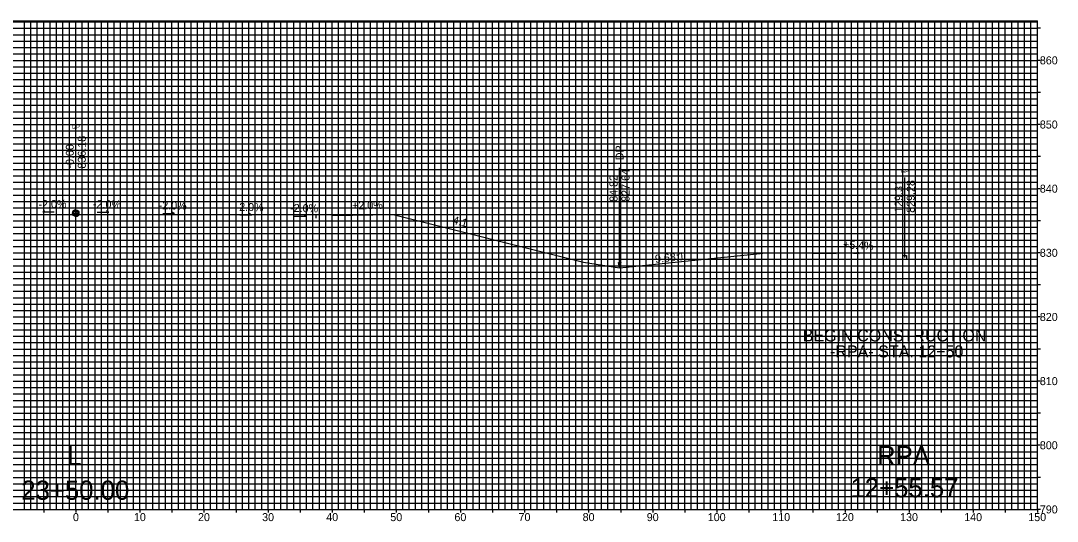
# Model space of a CAD drawing. Extents: x -153 to 153, y 788 to 866.
# Drawn here: x -8.6 to 153.1, y 788.2 to 866.2 of the extents above; entities that cross this region are included whole.
import ezdxf

# ---------------------------------------------------------------- set-up
doc = ezdxf.new("R2010")
doc.units = 0
for name, color, linetype in [('Exist Utilities Power Transformer CELL', 7, 'Continuous'), ('P_NCDOT_XS_Label_Grade_Point', 7, 'Continuous'), ('P_NCDOT_XS_Label_Grading_Side_Slope', 7, 'Continuous'), ('P_NCDOT_XS_Label_Slope_Superelevation', 7, 'Continuous'), ('P_NCDOT_XS_Leader_Line', 7, 'Continuous'), ('P_NCDOT_XS_Sheet_Alignment_Station_Label', 7, 'Continuous'), ('P_NCDOT_XS_Sheet_Annotation_Label', 7, 'Continuous'), ('P_NCDOT_XS_Sheet_Grid_Border', 7, 'Continuous'), ('P_NCDOT_XS_Slope_Label', 7, 'Continuous'), ('P_RDY_XS_EOT_Tick_Mark', 7, 'Continuous'), ('Prop XS Grade Point', 7, 'Continuous'), ('Prop XS Label Slope Superelevation', 7, 'Continuous'), ('Sheet_Grid_Major', 7, 'Continuous'), ('Sheet_Grid_Middle', 7, 'Continuous'), ('Sheet_Grid_Minor', 7, 'Continuous')]:
    doc.layers.add(name, color=color, linetype=linetype)

msp = doc.modelspace()

# ---------------------------------------------------------------- linework, layer by layer
at = {"layer": 'Exist Utilities Power Transformer CELL'}
msp.add_lwpolyline([(40, 835.81), (49.5, 836), (79.2, 828.57), (84.82, 827.64), (106.75, 829.91), (108.03, 830.04), (114.91, 829.97), (118.64, 829.88)], dxfattribs=at)
at = {"layer": 'P_NCDOT_XS_Leader_Line'}
for p, q in [((0, 836.18), (0, 848.66)), ((84.82, 827.64), (84.82, 843.24)), ((129.31, 829.28), (129.31, 841.76))]:
    msp.add_line(p, q, dxfattribs=at)
for points in [[(0.3, 835.88), (-0.3, 835.88), (-0.3, 836.48), (0.3, 836.48)], [(129.61, 828.98), (129.01, 828.98), (129.01, 829.58), (129.61, 829.58)], [(84.82, 827.64), (84.65, 828.47), (85, 828.47)]]:
    msp.add_lwpolyline(points, close=True, dxfattribs=at)
at = {"layer": 'P_NCDOT_XS_Sheet_Grid_Border'}
for p, q in [((-150, 866.18), (150, 866.18)), ((150, 790), (150, 866.18)), ((-150, 790), (150, 790))]:
    msp.add_line(p, q, dxfattribs=at)
at = {"layer": 'P_RDY_XS_EOT_Tick_Mark'}
for p, q in [((37.5, 835.43), (37.5, 836.05)), ((124, 829.59), (124, 830.21))]:
    msp.add_line(p, q, dxfattribs=at)
at = {"layer": 'Prop XS Grade Point'}
for p, q in [((-0.5, 836.18), (0.5, 836.18)), ((0, 836.68), (0, 835.68))]:
    msp.add_line(p, q, dxfattribs=at)
for points in [[(-0.5, 836.18), (0, 836.18), (0, 836.68)], [(0.5, 836.18), (0, 836.18), (0, 835.68)]]:
    msp.add_lwpolyline(points, dxfattribs=at)
msp.add_circle((0, 836.18), 0.5, dxfattribs=at)
for start, end in [(90, 180), (270, 0)]:
    msp.add_arc((0, 836.18), 0.5, start, end, dxfattribs=at)
at = {"layer": 'Prop XS Label Slope Superelevation'}
for p, q in [((-5.15, 836.32), (-4.81, 836.57)), ((-3.35, 836.35), (-5.15, 836.32)), ((3.35, 836.35), (5.15, 836.32)), ((5.15, 836.32), (4.81, 836.57)), ((13.6, 836.15), (15.4, 836.11)), ((15.4, 836.11), (15.06, 836.36)), ((27.4, 835.87), (27.06, 836.12)), ((25.6, 835.91), (27.4, 835.87)), ((34.1, 835.74), (35.9, 835.7)), ((35.9, 835.7), (35.56, 835.95)), ((120.42, 830.02), (122.21, 829.92)), ((122.21, 829.92), (121.88, 830.18))]:
    msp.add_line(p, q, dxfattribs=at)
at = {"layer": 'Sheet_Grid_Major'}
for p, q in [((0, 790), (0, 866.18)), ((10, 790), (10, 866.18)), ((20, 790), (20, 866.18)), ((30, 790), (30, 866.18)), ((40, 790), (40, 866.18)), ((50, 790), (50, 866.18)), ((60, 790), (60, 866.18)), ((70, 790), (70, 866.18)), ((80, 790), (80, 866.18)), ((90, 790), (90, 866.18)), ((100, 790), (100, 866.18)), ((110, 790), (110, 866.18)), ((120, 790), (120, 866.18)), ((130, 790), (130, 866.18)), ((140, 790), (140, 866.18)), ((-150, 860), (150, 860)), ((-150, 850), (150, 850)), ((-150, 840), (150, 840)), ((-150, 830), (150, 830)), ((-150, 820), (150, 820)), ((-150, 810), (150, 810)), ((-150, 800), (150, 800))]:
    msp.add_line(p, q, dxfattribs=at)
at = {"layer": 'Sheet_Grid_Middle'}
for p, q in [((-5, 790), (-5, 866.18)), ((0, 790), (0, 866.18)), ((5, 790), (5, 866.18)), ((10, 790), (10, 866.18)), ((15, 790), (15, 866.18)), ((20, 790), (20, 866.18)), ((25, 790), (25, 866.18)), ((30, 790), (30, 866.18)), ((35, 790), (35, 866.18)), ((40, 790), (40, 866.18)), ((45, 790), (45, 866.18)), ((50, 790), (50, 866.18)), ((55, 790), (55, 866.18)), ((60, 790), (60, 866.18)), ((65, 790), (65, 866.18)), ((70, 790), (70, 866.18)), ((75, 790), (75, 866.18)), ((80, 790), (80, 866.18)), ((85, 790), (85, 866.18)), ((90, 790), (90, 866.18)), ((95, 790), (95, 866.18)), ((100, 790), (100, 866.18)), ((105, 790), (105, 866.18)), ((110, 790), (110, 866.18)), ((115, 790), (115, 866.18)), ((120, 790), (120, 866.18)), ((125, 790), (125, 866.18)), ((130, 790), (130, 866.18)), ((135, 790), (135, 866.18)), ((140, 790), (140, 866.18)), ((145, 790), (145, 866.18)), ((-150, 865), (150, 865)), ((150.48, 865), (150, 865)), ((-150, 860), (150, 860)), ((150.48, 860), (150, 860)), ((-150, 855), (150, 855)), ((150.48, 855), (150, 855)), ((-150, 850), (150, 850)), ((150.48, 850), (150, 850)), ((-150, 845), (150, 845)), ((150.48, 845), (150, 845)), ((-150, 840), (150, 840)), ((150.48, 840), (150, 840)), ((-150, 835), (150, 835)), ((150.48, 835), (150, 835)), ((-150, 830), (150, 830)), ((150.48, 830), (150, 830)), ((-150, 825), (150, 825)), ((150.48, 825), (150, 825)), ((-150, 820), (150, 820)), ((150.48, 820), (150, 820)), ((-150, 815), (150, 815)), ((150.48, 815), (150, 815)), ((-150, 810), (150, 810)), ((150.48, 810), (150, 810)), ((-150, 805), (150, 805)), ((150.48, 805), (150, 805)), ((-150, 800), (150, 800)), ((150.48, 800), (150, 800)), ((-150, 795), (150, 795)), ((150.48, 795), (150, 795)), ((-5, 790), (-5, 789.52)), ((0, 790), (0, 789.52)), ((5, 790), (5, 789.52)), ((10, 790), (10, 789.52)), ((15, 790), (15, 789.52)), ((20, 790), (20, 789.52)), ((25, 790), (25, 789.52)), ((30, 790), (30, 789.52)), ((35, 790), (35, 789.52)), ((40, 790), (40, 789.52)), ((45, 790), (45, 789.52)), ((50, 790), (50, 789.52)), ((55, 790), (55, 789.52)), ((60, 790), (60, 789.52)), ((65, 790), (65, 789.52)), ((70, 790), (70, 789.52)), ((75, 790), (75, 789.52)), ((80, 790), (80, 789.52)), ((85, 790), (85, 789.52)), ((90, 790), (90, 789.52)), ((95, 790), (95, 789.52)), ((100, 790), (100, 789.52)), ((105, 790), (105, 789.52)), ((110, 790), (110, 789.52)), ((115, 790), (115, 789.52)), ((120, 790), (120, 789.52)), ((125, 790), (125, 789.52)), ((130, 790), (130, 789.52)), ((135, 790), (135, 789.52)), ((140, 790), (140, 789.52)), ((145, 790), (145, 789.52)), ((150, 790), (150, 789.52)), ((150.48, 790), (150, 790))]:
    msp.add_line(p, q, dxfattribs=at)
at = {"layer": 'Sheet_Grid_Minor'}
for p, q in [((-150, 866), (150, 866)), ((-8, 790), (-8, 866.18)), ((-7, 790), (-7, 866.18)), ((-6, 790), (-6, 866.18)), ((-4, 790), (-4, 866.18)), ((-3, 790), (-3, 866.18)), ((-2, 790), (-2, 866.18)), ((-1, 790), (-1, 866.18)), ((1, 790), (1, 866.18)), ((2, 790), (2, 866.18)), ((3, 790), (3, 866.18)), ((4, 790), (4, 866.18)), ((6, 790), (6, 866.18)), ((7, 790), (7, 866.18)), ((8, 790), (8, 866.18)), ((9, 790), (9, 866.18)), ((11, 790), (11, 866.18)), ((12, 790), (12, 866.18)), ((13, 790), (13, 866.18)), ((14, 790), (14, 866.18)), ((16, 790), (16, 866.18)), ((17, 790), (17, 866.18)), ((18, 790), (18, 866.18)), ((19, 790), (19, 866.18)), ((21, 790), (21, 866.18)), ((22, 790), (22, 866.18)), ((23, 790), (23, 866.18)), ((24, 790), (24, 866.18)), ((26, 790), (26, 866.18)), ((27, 790), (27, 866.18)), ((28, 790), (28, 866.18)), ((29, 790), (29, 866.18)), ((31, 790), (31, 866.18)), ((32, 790), (32, 866.18)), ((33, 790), (33, 866.18)), ((34, 790), (34, 866.18)), ((36, 790), (36, 866.18)), ((37, 790), (37, 866.18)), ((38, 790), (38, 866.18)), ((39, 790), (39, 866.18)), ((41, 790), (41, 866.18)), ((42, 790), (42, 866.18)), ((43, 790), (43, 866.18)), ((44, 790), (44, 866.18)), ((46, 790), (46, 866.18)), ((47, 790), (47, 866.18)), ((48, 790), (48, 866.18)), ((49, 790), (49, 866.18)), ((51, 790), (51, 866.18)), ((52, 790), (52, 866.18)), ((53, 790), (53, 866.18)), ((54, 790), (54, 866.18)), ((56, 790), (56, 866.18)), ((57, 790), (57, 866.18)), ((58, 790), (58, 866.18)), ((59, 790), (59, 866.18)), ((61, 790), (61, 866.18)), ((62, 790), (62, 866.18)), ((63, 790), (63, 866.18)), ((64, 790), (64, 866.18)), ((66, 790), (66, 866.18)), ((67, 790), (67, 866.18)), ((68, 790), (68, 866.18)), ((69, 790), (69, 866.18)), ((71, 790), (71, 866.18)), ((72, 790), (72, 866.18)), ((73, 790), (73, 866.18)), ((74, 790), (74, 866.18)), ((76, 790), (76, 866.18)), ((77, 790), (77, 866.18)), ((78, 790), (78, 866.18)), ((79, 790), (79, 866.18)), ((81, 790), (81, 866.18)), ((82, 790), (82, 866.18)), ((83, 790), (83, 866.18)), ((84, 790), (84, 866.18)), ((86, 790), (86, 866.18)), ((87, 790), (87, 866.18)), ((88, 790), (88, 866.18)), ((89, 790), (89, 866.18)), ((91, 790), (91, 866.18)), ((92, 790), (92, 866.18)), ((93, 790), (93, 866.18)), ((94, 790), (94, 866.18)), ((96, 790), (96, 866.18)), ((97, 790), (97, 866.18)), ((98, 790), (98, 866.18)), ((99, 790), (99, 866.18)), ((101, 790), (101, 866.18)), ((102, 790), (102, 866.18)), ((103, 790), (103, 866.18)), ((104, 790), (104, 866.18)), ((106, 790), (106, 866.18)), ((107, 790), (107, 866.18)), ((108, 790), (108, 866.18)), ((109, 790), (109, 866.18)), ((111, 790), (111, 866.18)), ((112, 790), (112, 866.18)), ((113, 790), (113, 866.18)), ((114, 790), (114, 866.18)), ((116, 790), (116, 866.18)), ((117, 790), (117, 866.18)), ((118, 790), (118, 866.18)), ((119, 790), (119, 866.18)), ((121, 790), (121, 866.18)), ((122, 790), (122, 866.18)), ((123, 790), (123, 866.18)), ((124, 790), (124, 866.18)), ((126, 790), (126, 866.18)), ((127, 790), (127, 866.18)), ((128, 790), (128, 866.18)), ((129, 790), (129, 866.18)), ((131, 790), (131, 866.18)), ((132, 790), (132, 866.18)), ((133, 790), (133, 866.18)), ((134, 790), (134, 866.18)), ((136, 790), (136, 866.18)), ((137, 790), (137, 866.18)), ((138, 790), (138, 866.18)), ((139, 790), (139, 866.18)), ((141, 790), (141, 866.18)), ((142, 790), (142, 866.18)), ((143, 790), (143, 866.18)), ((144, 790), (144, 866.18)), ((146, 790), (146, 866.18)), ((147, 790), (147, 866.18)), ((148, 790), (148, 866.18)), ((149, 790), (149, 866.18)), ((-150, 864), (150, 864)), ((-150, 863), (150, 863)), ((-150, 862), (150, 862)), ((-150, 861), (150, 861)), ((-150, 859), (150, 859)), ((-150, 858), (150, 858)), ((-150, 857), (150, 857)), ((-150, 856), (150, 856)), ((-150, 854), (150, 854)), ((-150, 853), (150, 853)), ((-150, 852), (150, 852)), ((-150, 851), (150, 851)), ((-150, 849), (150, 849)), ((-150, 848), (150, 848)), ((-150, 847), (150, 847)), ((-150, 846), (150, 846)), ((-150, 844), (150, 844)), ((-150, 843), (150, 843)), ((-150, 842), (150, 842)), ((-150, 841), (150, 841)), ((-150, 839), (150, 839)), ((-150, 838), (150, 838)), ((-150, 837), (150, 837)), ((-150, 836), (150, 836)), ((-150, 834), (150, 834)), ((-150, 833), (150, 833)), ((-150, 832), (150, 832)), ((-150, 831), (150, 831)), ((-150, 829), (150, 829)), ((-150, 828), (150, 828)), ((-150, 827), (150, 827)), ((-150, 826), (150, 826)), ((-150, 824), (150, 824)), ((-150, 823), (150, 823)), ((-150, 822), (150, 822)), ((-150, 821), (150, 821)), ((-150, 819), (150, 819)), ((-150, 818), (150, 818)), ((-150, 817), (150, 817)), ((-150, 816), (150, 816)), ((-150, 814), (150, 814)), ((-150, 813), (150, 813)), ((-150, 812), (150, 812)), ((-150, 811), (150, 811)), ((-150, 809), (150, 809)), ((-150, 808), (150, 808)), ((-150, 807), (150, 807)), ((-150, 806), (150, 806)), ((-150, 804), (150, 804)), ((-150, 803), (150, 803)), ((-150, 802), (150, 802)), ((-150, 801), (150, 801)), ((-150, 799), (150, 799)), ((-150, 798), (150, 798)), ((-150, 797), (150, 797)), ((-150, 796), (150, 796)), ((-150, 794), (150, 794)), ((-150, 793), (150, 793)), ((-150, 792), (150, 792)), ((-150, 791), (150, 791))]:
    msp.add_line(p, q, dxfattribs=at)

# ---------------------------------------------------------------- texts
at = {"layer": 'P_NCDOT_XS_Label_Grade_Point'}
for s, height, p in [('GP', 0.624, (-0.61, 849.32)), ('GP', 0.624, (128.7, 842.43)), ('BEGIN CONSTRUCTION', 1.872, (113.41, 816.19)), ('-RPA- STA. 12+50', 1.872, (117.66, 813.7))]:
    msp.add_text(s, height=height, dxfattribs=at).set_placement(p)
for s, p in [('836.18', (1.56, 843.14)), ('-0.00', (-0.31, 843.14)), ('129.31', (129, 836.24)), ('829.28', (130.87, 836.24))]:
    msp.add_text(s, height=1.248, rotation=90, dxfattribs=at).set_placement(p)
at = {"layer": 'P_NCDOT_XS_Label_Grading_Side_Slope'}
for s, p in [('DP', (85.45, 844.44)), ('827.64', (86.38, 837.96)), ('84.82', (84.51, 837.96))]:
    msp.add_text(s, height=1.248, rotation=90, dxfattribs=at).set_placement(p)
at = {"layer": 'P_NCDOT_XS_Label_Slope_Superelevation'}
for rotation, p in [(1.1458, (-5.8, 836.94)), (358.8542, (2.68, 837)), (358.8542, (12.93, 836.8)), (358.8542, (24.93, 836.56)), (358.8542, (33.43, 836.39))]:
    msp.add_text('-2.0%', height=1.248, rotation=rotation, dxfattribs=at).set_placement(p)
at = {"layer": 'P_NCDOT_XS_Sheet_Alignment_Station_Label'}
for s, p in [('L', (-1.32, 796.9)), ('RPA', (125, 796.9)), ('23+50.00', (-8.5, 791.5)), ('12+55.57', (120.85, 791.88))]:
    msp.add_text(s, height=3, dxfattribs=at).set_placement(p)
at = {"layer": 'P_NCDOT_XS_Sheet_Annotation_Label'}
for s, height, p in [('860', 1.248, (150.39, 859.38)), ('850', 1.248, (150.39, 849.38)), ('840', 1.248, (150.39, 839.38)), ('830', 1.248, (150.39, 829.38)), ('820', 1.248, (150.39, 819.38)), ('810', 1.248, (150.39, 809.38)), ('800', 1.248, (150.39, 799.38)), ('0', 1.25, (-0.44, 788.18)), ('10', 1.248, (9.07, 788.18)), ('20', 1.248, (19.07, 788.18)), ('30', 1.248, (29.07, 788.18)), ('40', 1.248, (39.07, 788.18)), ('50', 1.248, (49.07, 788.18)), ('60', 1.248, (59.07, 788.18)), ('70', 1.248, (69.07, 788.18)), ('80', 1.248, (79.07, 788.18)), ('90', 1.248, (89.07, 788.18)), ('100', 1.248, (98.59, 788.18)), ('110', 1.248, (108.65, 788.18)), ('120', 1.248, (118.59, 788.18)), ('130', 1.248, (128.59, 788.18)), ('140', 1.248, (138.59, 788.18)), ('150', 1.248, (148.59, 788.18)), ('790', 1.248, (150.39, 789.38))]:
    msp.add_text(s, height=height, dxfattribs=at).set_placement(p)
at = {"layer": 'P_NCDOT_XS_Slope_Label'}
for s, rotation, p in [('+2.0%', 1.1458, (43.11, 836.75)), ('4:1', 345.9638, (58.69, 834.56)), ('+5.4%', 356.8872, (119.66, 830.7)), ('9.68:1', 5.8957, (90.42, 828.43))]:
    msp.add_text(s, height=1.248, rotation=rotation, dxfattribs=at).set_placement(p)

doc.saveas('drawing.dxf')
